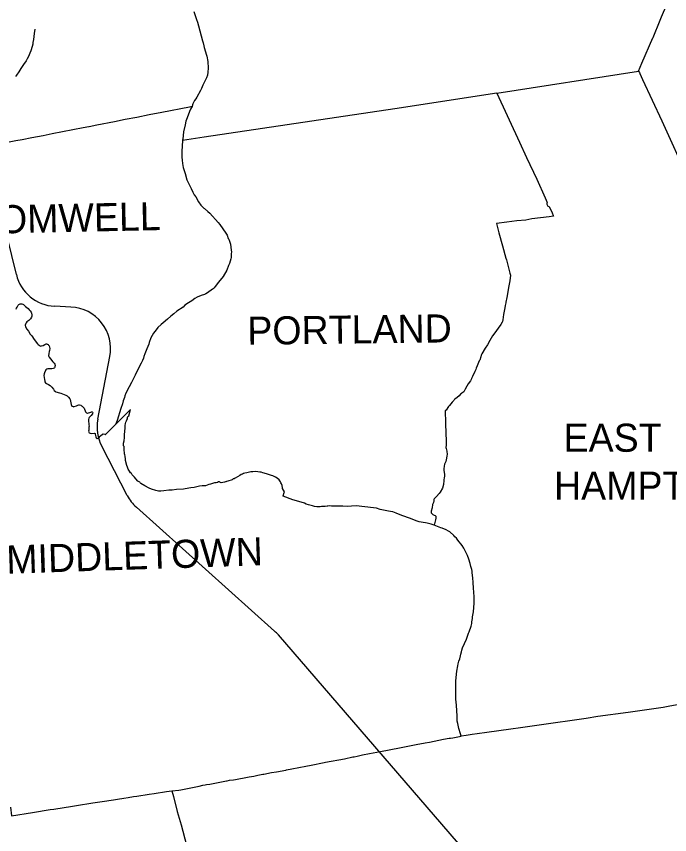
# Model space of a CAD drawing. Extents: x 0 to 2603, y -226 to 830.
# Drawn here: x 204.97 to 236.38, y 575 to 614.31 of the extents above; entities that cross this region are included whole.
import ezdxf

# ---------------------------------------------------------------- set-up
doc = ezdxf.new("R2010")
doc.units = 0
for name, color, linetype in [('CT_TSH_Map_Districts', 7, 'Continuous'), ('CT_TSH_Map_Interstate_Roads', 7, 'Continuous'), ('CT_TSH_Map_Town_Limits', 7, 'Continuous'), ('CT_TSH_Map_Town_Text', 7, 'Continuous'), ('CT_TSH_Map_US_and_State_Routes', 7, 'Continuous')]:
    doc.layers.add(name, color=color, linetype=linetype)

msp = doc.modelspace()

# ---------------------------------------------------------------- linework, layer by layer
at = {"layer": 'CT_TSH_Map_Districts'}
for points in [[(234.884, 611.677), (235.041, 612.051), (235.566, 613.271), (235.579, 613.297), (235.927, 614.12), (235.983, 614.28), (236.084, 614.51), (236.428, 615.301), (240.127, 616.807), (239.953, 617.904), (239.072, 619.882), (239.607, 620.4), (239.988, 620.781), (244.272, 621.425)], [(228.072, 610.617), (234.884, 611.677)], [(228.072, 610.617), (223.173, 609.87), (214.002, 608.502), (212.956, 608.343)], [(212.956, 608.343), (212.919, 607.819), (212.92, 607.548), (212.941, 607.396), (212.953, 607.242), (212.989, 607.041), (213.077, 606.758), (213.166, 606.45), (213.207, 606.351), (213.292, 606.189), (213.377, 606.037), (213.45, 605.861), (213.517, 605.736), (213.592, 605.636), (213.728, 605.397), (213.834, 605.242), (213.98, 605.086), (214.009, 605.072), (214.182, 604.924), (214.267, 604.843), (214.672, 604.397), (214.748, 604.3), (215.04, 603.891), (215.098, 603.801), (215.157, 603.637), (215.18, 603.603), (215.263, 603.365), (215.302, 603.068), (215.307, 603.001), (215.301, 602.894), (215.296, 602.882), (215.291, 602.725), (215.278, 602.658), (215.212, 602.439), (215.175, 602.33), (215.083, 602.105), (214.905, 601.801), (214.686, 601.533), (214.532, 601.323), (214.486, 601.269), (214.43, 601.211), (214.407, 601.198), (214.157, 601.022), (214.086, 600.979), (214.014, 600.94), (213.85, 600.892), (213.657, 600.81), (213.545, 600.745), (213.411, 600.646), (213.242, 600.544), (213.074, 600.424), (212.982, 600.341), (212.687, 600.141), (212.544, 600.015), (212.394, 599.906), (212.241, 599.766), (212.026, 599.579), (211.937, 599.507), (211.773, 599.352), (211.685, 599.251), (211.559, 599.086), (211.439, 598.863), (211.357, 598.641), (211.338, 598.562), (211.249, 598.338), (211.142, 598.086), (211.1, 597.968), (211.077, 597.882), (211.028, 597.767), (210.97, 597.649), (210.802, 597.336), (210.681, 597.076), (210.502, 596.719), (210.399, 596.505), (210.228, 596.208), (210.182, 596.071), (210.16, 595.993), (210.102, 595.839), (210.065, 595.685), (209.984, 595.472), (209.811, 594.898), (209.757, 594.733), (209.758, 594.717)], [(213.773, 591.73), (213.517, 591.674), (213.357, 591.663), (213.259, 591.647), (213.176, 591.619), (213.091, 591.61), (213.004, 591.593), (212.661, 591.577), (212.462, 591.544), (212.37, 591.545), (212.307, 591.54), (212.066, 591.504), (211.907, 591.492), (211.799, 591.498), (211.681, 591.524), (211.47, 591.596), (211.359, 591.638), (211.14, 591.746), (210.961, 591.861), (210.919, 591.898), (210.899, 591.923), (210.815, 591.974), (210.707, 592.091), (210.643, 592.175), (210.533, 592.288), (210.499, 592.341), (210.459, 592.383), (210.402, 592.46), (210.352, 592.55), (210.308, 592.647), (210.276, 592.732), (210.215, 592.967), (210.223, 593.027), (210.192, 593.185), (210.186, 593.239), (210.172, 593.288), (210.155, 593.521), (210.155, 593.614), (210.145, 593.644), (210.124, 593.68), (210.118, 593.719), (210.122, 593.796), (210.149, 593.907), (210.165, 594.072), (210.164, 594.198), (210.204, 594.538), (210.198, 594.647), (210.215, 594.748), (210.236, 594.81), (210.266, 594.871), (210.287, 594.928), (210.311, 594.971), (210.317, 595.058), (210.331, 595.09), (210.374, 595.113), (210.455, 595.413), (209.758, 594.717)], [(225.049, 589.87), (224.908, 589.917), (224.725, 589.964), (224.635, 589.968), (224.525, 589.989), (224.431, 589.999), (224.335, 590.022), (224.186, 590.069), (223.912, 590.183), (223.497, 590.325), (223.23, 590.444), (223.145, 590.476), (223.069, 590.496), (222.955, 590.517), (222.867, 590.541), (222.616, 590.583), (222.461, 590.619), (222.279, 590.676), (222.136, 590.7), (221.731, 590.751), (221.301, 590.789), (221.088, 590.773), (220.876, 590.763), (220.668, 590.772), (220.125, 590.776), (220.016, 590.786), (219.944, 590.774), (219.916, 590.777), (219.822, 590.765), (219.731, 590.763), (219.637, 590.756), (219.583, 590.743), (219.41, 590.749), (219.307, 590.765), (219.209, 590.788), (219.082, 590.826), (219.007, 590.835), (218.903, 590.875), (218.822, 590.912), (218.444, 591.026), (218.259, 591.076), (217.791, 591.25), (217.797, 591.278), (217.848, 591.426), (217.855, 591.459), (217.864, 591.468), (217.771, 591.624), (217.757, 591.66), (217.741, 591.767), (217.714, 591.853), (217.69, 591.902), (217.667, 591.937), (217.644, 591.986), (217.599, 592.045), (217.506, 592.122), (217.426, 592.164), (217.356, 592.207), (217.296, 592.225), (217.233, 592.254), (217.145, 592.28), (216.997, 592.335), (216.824, 592.37), (216.744, 592.405), (216.671, 592.414), (216.586, 592.432), (216.451, 592.433), (216.339, 592.427), (216.249, 592.417), (216.048, 592.38), (215.958, 592.359), (215.883, 592.337), (215.847, 592.315), (215.773, 592.295), (215.712, 592.241), (215.481, 592.115), (215.435, 592.096), (215.397, 592.087), (215.379, 592.067), (215.337, 592.039), (215.135, 591.975), (215.065, 591.953), (215.04, 591.952), (215.017, 591.938), (214.983, 591.925), (214.89, 591.907), (214.812, 591.901), (214.753, 591.927), (214.731, 591.947), (214.66, 591.941), (214.656, 591.928), (214.636, 591.909), (214.578, 591.892), (214.503, 591.896), (214.394, 591.86), (214.309, 591.832), (214.226, 591.818), (214.057, 591.754), (214.026, 591.757), (213.966, 591.752), (213.905, 591.75), (213.773, 591.73)], [(226.349, 579.726), (226.325, 579.833), (226.247, 580.094), (226.188, 580.338), (226.17, 580.445), (226.165, 580.68), (226.129, 581.223), (226.1, 581.496), (226.105, 581.645), (226.096, 582.142), (226.099, 582.363), (226.124, 582.697), (226.142, 582.849), (226.194, 583.107), (226.211, 583.198), (226.249, 583.334), (226.287, 583.445), (226.322, 583.583), (226.333, 583.661), (226.373, 583.777), (226.389, 583.861), (226.423, 583.965), (226.514, 584.178), (226.61, 584.384), (226.711, 584.668), (226.741, 584.732), (226.834, 585.014), (226.866, 585.144), (226.871, 585.219), (226.887, 585.292), (226.893, 585.385), (226.905, 585.461), (226.923, 585.541), (226.943, 585.699), (226.977, 586.119), (226.988, 586.418), (226.967, 586.64), (226.956, 586.833), (226.931, 587.105), (226.919, 587.339), (226.891, 587.567), (226.887, 587.646), (226.872, 587.729), (226.824, 587.882), (226.789, 588.026), (226.716, 588.222), (226.655, 588.402), (226.537, 588.654), (226.487, 588.75), (226.399, 588.892), (226.19, 589.146), (226.123, 589.236), (226.051, 589.307), (226.002, 589.367), (225.807, 589.539), (225.753, 589.579), (225.637, 589.646), (225.44, 589.724), (225.382, 589.737), (225.063, 589.86), (225.049, 589.87)], [(212.436, 577.103), (212.779, 577.13), (212.872, 577.144), (213.755, 577.331), (213.94, 577.374), (214.047, 577.394), (214.109, 577.398), (214.27, 577.421), (215.068, 577.574), (215.111, 577.58), (215.221, 577.606), (215.405, 577.625), (215.499, 577.651), (215.584, 577.668), (216.007, 577.737), (216.157, 577.769), (216.379, 577.806), (216.576, 577.847), (216.812, 577.894), (216.862, 577.908), (217.239, 577.975), (217.471, 578.008), (217.925, 578.1), (217.952, 578.103), (218.218, 578.161), (218.881, 578.282), (219.136, 578.338), (219.761, 578.461), (219.834, 578.476), (220.744, 578.638), (221.139, 578.73), (221.218, 578.738), (221.352, 578.77), (221.476, 578.796), (221.604, 578.828), (221.95, 578.887), (222.471, 578.993), (223.397, 579.171), (224.186, 579.32), (224.62, 579.411), (224.831, 579.443), (225.503, 579.576), (225.773, 579.623), (225.841, 579.632), (225.962, 579.652), (226.108, 579.684), (226.349, 579.726)], [(212.436, 577.103), (212.517, 576.826), (212.708, 576.115), (212.888, 575.462), (213.152, 574.484)]]:
    msp.add_lwpolyline(points, dxfattribs=at)
at = {"layer": 'CT_TSH_Map_Interstate_Roads'}
for points in [[(205.85, 613.695), (205.824, 613.48), (205.79, 613.199)], [(205.768, 613.051), (205.753, 612.972), (205.733, 612.863), (205.668, 612.652), (205.619, 612.538), (205.546, 612.38), (205.486, 612.268)], [(205.79, 613.199), (205.768, 613.051)], [(205.486, 612.268), (205.433, 612.173), (205.311, 611.987), (205.187, 611.796), (205.084, 611.638), (204.97, 611.479)], [(204.97, 611.479), (204.929, 611.423)]]:
    msp.add_lwpolyline(points, dxfattribs=at)
at = {"layer": 'CT_TSH_Map_Town_Limits'}
for points in [[(234.884, 611.677), (235.041, 612.051), (235.566, 613.271), (235.579, 613.297), (235.927, 614.12), (235.983, 614.28), (236.084, 614.51), (236.428, 615.301), (240.127, 616.807), (239.953, 617.904), (239.072, 619.882), (239.607, 620.4), (239.988, 620.781), (244.272, 621.425)], [(213.495, 614.539), (213.628, 614.158), (213.677, 614.031), (213.722, 613.844), (213.795, 613.607), (213.915, 613.133), (213.945, 613.038), (213.975, 612.89), (213.997, 612.817), (214.018, 612.767), (214.1, 612.482), (214.121, 612.399), (214.169, 612.132), (214.189, 611.818), (214.178, 611.621), (214.153, 611.478), (214.109, 611.346), (214.067, 611.252), (213.999, 611.126), (213.977, 611.097), (213.941, 611.002), (213.868, 610.832), (213.826, 610.747), (213.647, 610.425), (213.597, 610.342), (213.539, 610.26), (213.446, 610.1), (213.43, 610.051), (213.423, 609.978)], [(228.072, 610.617), (234.884, 611.677)], [(234.884, 611.677), (234.922, 611.605), (234.945, 611.566), (235.077, 611.27), (235.998, 609.281), (237.269, 606.502), (239.719, 601.253), (240.373, 599.873), (240.571, 599.445), (240.652, 599.27), (240.867, 598.805), (240.916, 598.702), (241.403, 597.685), (241.795, 596.836), (241.83, 596.77)], [(228.072, 610.617), (223.173, 609.87), (214.002, 608.502), (212.956, 608.343)], [(228.072, 610.617), (229.157, 608.258), (229.496, 607.532), (229.986, 606.482), (230.39, 605.58), (230.487, 605.366), (230.487, 605.361), (230.479, 605.335), (230.475, 605.289), (230.489, 605.245), (230.524, 605.195), (230.579, 605.172), (230.582, 605.168), (230.723, 604.86), (230.784, 604.732), (230.793, 604.703), (230.58, 604.679), (229.758, 604.572), (229.458, 604.522), (229.031, 604.476), (228.548, 604.412), (228.048, 604.356), (228.172, 603.904), (228.342, 603.282), (228.504, 602.695), (228.531, 602.605), (228.701, 601.964), (228.734, 601.873), (228.689, 601.593), (228.623, 601.277), (228.577, 600.978), (228.544, 600.803), (228.506, 600.581), (228.498, 600.543), (228.474, 600.41), (228.462, 600.308), (228.394, 599.982), (228.362, 599.72), (228.337, 599.64), (228.333, 599.611), (228.256, 599.497), (227.931, 599.044), (227.862, 598.957), (227.799, 598.853), (227.738, 598.734), (227.621, 598.524), (227.508, 598.361), (227.341, 598.093), (227.317, 598.029), (227.298, 597.953), (227.247, 597.797), (227.222, 597.754), (227.118, 597.516), (227.077, 597.406), (227.055, 597.342), (227.011, 597.244), (226.892, 597.005), (226.866, 596.944), (226.858, 596.902), (226.849, 596.896), (226.798, 596.797), (226.698, 596.652), (226.698, 596.649), (226.625, 596.534), (226.545, 596.4), (226.494, 596.307), (226.476, 596.272), (226.394, 596.196), (226.379, 596.188), (226.33, 596.148), (226.254, 596.076), (226.155, 596.002), (226.049, 595.915), (226.021, 595.882), (225.999, 595.849), (225.928, 595.774), (225.799, 595.614), (225.745, 595.56), (225.627, 595.395), (225.59, 595.359), (225.59, 595.27), (225.6, 594.854), (225.609, 594.731), (225.607, 594.599), (225.625, 594.422), (225.639, 593.77), (225.638, 593.714), (225.632, 593.658), (225.621, 593.626), (225.623, 593.586), (225.64, 593.545), (225.667, 593.413), (225.678, 593.258), (225.668, 593.187), (225.645, 593.082), (225.635, 593.004), (225.617, 592.922), (225.558, 592.788), (225.536, 592.703), (225.52, 592.565), (225.525, 592.494)], [(213.423, 609.978), (213.297, 609.949), (211.955, 609.685), (211.36, 609.572), (210.76, 609.453), (210.205, 609.348), (209.692, 609.243), (208.832, 609.076), (208.469, 609.004), (208.446, 608.993), (208.174, 608.951), (206.69, 608.66), (206.258, 608.572), (205.711, 608.47), (205.252, 608.376), (204.946, 608.324), (204.548, 608.245), (204.102, 608.164), (202.012, 607.761), (201.589, 607.676), (200.476, 607.465), (198.272, 607.038)], [(213.423, 609.978), (213.392, 609.934), (213.347, 609.849), (213.297, 609.734), (213.182, 609.427), (213.121, 609.269), (213.078, 609.098), (213.008, 608.758), (212.971, 608.413), (212.956, 608.362), (212.956, 608.343)], [(212.956, 608.343), (212.919, 607.819), (212.92, 607.548), (212.941, 607.396), (212.953, 607.242), (212.989, 607.041), (213.077, 606.758), (213.166, 606.45), (213.207, 606.351), (213.292, 606.189), (213.377, 606.037), (213.45, 605.861), (213.517, 605.736), (213.592, 605.636), (213.728, 605.397), (213.834, 605.242), (213.98, 605.086), (214.009, 605.072), (214.182, 604.924), (214.267, 604.843), (214.672, 604.397), (214.748, 604.3), (215.04, 603.891), (215.098, 603.801), (215.157, 603.637), (215.18, 603.603), (215.263, 603.365), (215.302, 603.068), (215.307, 603.001), (215.301, 602.894), (215.296, 602.882), (215.291, 602.725), (215.278, 602.658), (215.212, 602.439), (215.175, 602.33), (215.083, 602.105), (214.905, 601.801), (214.686, 601.533), (214.532, 601.323), (214.486, 601.269), (214.43, 601.211), (214.407, 601.198), (214.157, 601.022), (214.086, 600.979), (214.014, 600.94), (213.85, 600.892), (213.657, 600.81), (213.545, 600.745), (213.411, 600.646), (213.242, 600.544), (213.074, 600.424), (212.982, 600.341), (212.687, 600.141), (212.544, 600.015), (212.394, 599.906), (212.241, 599.766), (212.026, 599.579), (211.937, 599.507), (211.773, 599.352), (211.685, 599.251), (211.559, 599.086), (211.439, 598.863), (211.357, 598.641), (211.338, 598.562), (211.249, 598.338), (211.142, 598.086), (211.1, 597.968), (211.077, 597.882), (211.028, 597.767), (210.97, 597.649), (210.802, 597.336), (210.681, 597.076), (210.502, 596.719), (210.399, 596.505), (210.228, 596.208), (210.182, 596.071), (210.16, 595.993), (210.102, 595.839), (210.065, 595.685), (209.984, 595.472), (209.811, 594.898), (209.757, 594.733), (209.758, 594.717)], [(204.954, 600.237), (204.981, 600.286), (205, 600.342), (205.055, 600.428), (205.084, 600.46), (205.117, 600.486), (205.148, 600.498), (205.229, 600.498), (205.275, 600.485), (205.309, 600.467)], [(205.309, 600.467), (205.414, 600.372), (205.543, 600.264), (205.586, 600.212), (205.639, 600.164), (205.677, 600.1), (205.704, 600.04), (205.719, 599.961), (205.715, 599.901), (205.703, 599.858), (205.656, 599.774), (205.575, 599.696), (205.468, 599.626), (205.436, 599.584), (205.406, 599.522), (205.398, 599.47), (205.411, 599.384), (205.478, 599.273), (205.548, 599.186), (205.632, 599.044), (205.708, 598.953), (205.83, 598.777), (205.992, 598.575), (206.02, 598.541), (206.106, 598.482), (206.153, 598.469), (206.183, 598.471), (206.256, 598.495), (206.344, 598.545), (206.402, 598.567), (206.429, 598.569), (206.447, 598.564), (206.491, 598.537), (206.519, 598.506), (206.542, 598.471), (206.565, 598.414), (206.58, 598.354), (206.568, 598.261), (206.551, 598.198), (206.527, 598.116), (206.515, 598.002), (206.546, 597.929), (206.602, 597.847), (206.726, 597.702), (206.786, 597.645), (206.812, 597.596), (206.829, 597.526), (206.826, 597.481), (206.818, 597.452), (206.8, 597.418), (206.788, 597.404), (206.746, 597.386), (206.678, 597.375), (206.56, 597.375), (206.504, 597.378), (206.474, 597.374), (206.427, 597.36), (206.391, 597.317), (206.329, 597.186), (206.309, 597.129), (206.297, 597.051), (206.328, 596.855), (206.332, 596.782), (206.34, 596.747), (206.364, 596.706), (206.417, 596.67), (206.512, 596.617), (206.589, 596.572), (206.668, 596.499), (206.759, 596.392), (206.793, 596.325), (206.844, 596.276), (206.866, 596.263), (207.048, 596.212), (207.11, 596.196), (207.347, 596.109), (207.415, 596.07), (207.48, 596.011), (207.542, 595.932), (207.553, 595.899), (207.597, 595.652), (207.633, 595.583), (207.649, 595.583), (207.699, 595.557), (207.723, 595.553), (207.748, 595.556), (207.857, 595.596), (207.925, 595.628), (207.977, 595.641), (208.003, 595.641), (208.063, 595.623), (208.095, 595.602), (208.129, 595.574), (208.166, 595.552), (208.224, 595.482), (208.299, 595.309), (208.312, 595.287), (208.344, 595.254), (208.366, 595.246), (208.389, 595.245), (208.549, 595.292)], [(208.549, 595.292), (208.589, 595.309), (208.608, 595.309), (208.635, 595.291), (208.64, 595.257), (208.635, 595.231), (208.626, 595.21), (208.566, 595.13), (208.503, 595.066), (208.474, 595.028), (208.456, 594.996), (208.443, 594.938), (208.44, 594.901), (208.46, 594.677), (208.468, 594.623), (208.459, 594.568), (208.448, 594.422), (208.444, 594.383), (208.448, 594.332), (208.464, 594.299), (208.512, 594.275), (208.564, 594.272), (208.727, 594.281), (208.752, 594.269), (208.765, 594.234), (208.793, 594.099), (208.81, 594.054), (208.834, 594.031), (208.851, 594.027), (208.907, 594.04), (208.933, 594.054), (208.954, 594.072), (208.982, 594.114), (209.014, 594.15), (209.109, 594.237), (209.137, 594.249), (209.215, 594.232), (209.238, 594.223), (209.247, 594.226), (209.758, 594.717)], [(213.773, 591.73), (213.517, 591.674), (213.357, 591.663), (213.259, 591.647), (213.176, 591.619), (213.091, 591.61), (213.004, 591.593), (212.661, 591.577), (212.462, 591.544), (212.37, 591.545), (212.307, 591.54), (212.066, 591.504), (211.907, 591.492), (211.799, 591.498), (211.681, 591.524), (211.47, 591.596), (211.359, 591.638), (211.14, 591.746), (210.961, 591.861), (210.919, 591.898), (210.899, 591.923), (210.815, 591.974), (210.707, 592.091), (210.643, 592.175), (210.533, 592.288), (210.499, 592.341), (210.459, 592.383), (210.402, 592.46), (210.352, 592.55), (210.308, 592.647), (210.276, 592.732), (210.215, 592.967), (210.223, 593.027), (210.192, 593.185), (210.186, 593.239), (210.172, 593.288), (210.155, 593.521), (210.155, 593.614), (210.145, 593.644), (210.124, 593.68), (210.118, 593.719), (210.122, 593.796), (210.149, 593.907), (210.165, 594.072), (210.164, 594.198), (210.204, 594.538), (210.198, 594.647), (210.215, 594.748), (210.236, 594.81), (210.266, 594.871), (210.287, 594.928), (210.311, 594.971), (210.317, 595.058), (210.331, 595.09), (210.374, 595.113), (210.455, 595.413), (209.758, 594.717)], [(225.049, 589.87), (224.908, 589.917), (224.725, 589.964), (224.635, 589.968), (224.525, 589.989), (224.431, 589.999), (224.335, 590.022), (224.186, 590.069), (223.912, 590.183), (223.497, 590.325), (223.23, 590.444), (223.145, 590.476), (223.069, 590.496), (222.955, 590.517), (222.867, 590.541), (222.616, 590.583), (222.461, 590.619), (222.279, 590.676), (222.136, 590.7), (221.731, 590.751), (221.301, 590.789), (221.088, 590.773), (220.876, 590.763), (220.668, 590.772), (220.125, 590.776), (220.016, 590.786), (219.944, 590.774), (219.916, 590.777), (219.822, 590.765), (219.731, 590.763), (219.637, 590.756), (219.583, 590.743), (219.41, 590.749), (219.307, 590.765), (219.209, 590.788), (219.082, 590.826), (219.007, 590.835), (218.903, 590.875), (218.822, 590.912), (218.444, 591.026), (218.259, 591.076), (217.791, 591.25), (217.797, 591.278), (217.848, 591.426), (217.855, 591.459), (217.864, 591.468), (217.771, 591.624), (217.757, 591.66), (217.741, 591.767), (217.714, 591.853), (217.69, 591.902), (217.667, 591.937), (217.644, 591.986), (217.599, 592.045), (217.506, 592.122), (217.426, 592.164), (217.356, 592.207), (217.296, 592.225), (217.233, 592.254), (217.145, 592.28), (216.997, 592.335), (216.824, 592.37), (216.744, 592.405), (216.671, 592.414), (216.586, 592.432), (216.451, 592.433), (216.339, 592.427), (216.249, 592.417), (216.048, 592.38), (215.958, 592.359), (215.883, 592.337), (215.847, 592.315), (215.773, 592.295), (215.712, 592.241), (215.481, 592.115), (215.435, 592.096), (215.397, 592.087), (215.379, 592.067), (215.337, 592.039), (215.135, 591.975), (215.065, 591.953), (215.04, 591.952), (215.017, 591.938), (214.983, 591.925), (214.89, 591.907), (214.812, 591.901), (214.753, 591.927), (214.731, 591.947), (214.66, 591.941), (214.656, 591.928), (214.636, 591.909), (214.578, 591.892), (214.503, 591.896), (214.394, 591.86), (214.309, 591.832), (214.226, 591.818), (214.057, 591.754), (214.026, 591.757), (213.966, 591.752), (213.905, 591.75), (213.773, 591.73)], [(225.525, 592.494), (225.546, 592.313), (225.554, 592.225), (225.54, 592.121), (225.526, 592.052), (225.526, 592.012), (225.505, 591.82), (225.46, 591.638), (225.338, 591.451), (225.304, 591.388), (225.166, 591.236), (225.075, 591.15), (225.049, 591.121), (225.048, 591.094), (225.042, 591.071), (225.039, 591.027), (225.024, 590.95), (224.97, 590.855), (224.961, 590.697), (224.917, 590.543), (224.913, 590.491), (224.917, 590.458), (224.941, 590.418), (224.999, 590.368), (225.052, 590.346), (225.111, 590.333), (225.127, 590.314), (225.133, 590.29), (225.131, 590.196), (225.116, 590.115), (225.049, 589.87)], [(226.349, 579.726), (226.325, 579.833), (226.247, 580.094), (226.188, 580.338), (226.17, 580.445), (226.165, 580.68), (226.129, 581.223), (226.1, 581.496), (226.105, 581.645), (226.096, 582.142), (226.099, 582.363), (226.124, 582.697), (226.142, 582.849), (226.194, 583.107), (226.211, 583.198), (226.249, 583.334), (226.287, 583.445), (226.322, 583.583), (226.333, 583.661), (226.373, 583.777), (226.389, 583.861), (226.423, 583.965), (226.514, 584.178), (226.61, 584.384), (226.711, 584.668), (226.741, 584.732), (226.834, 585.014), (226.866, 585.144), (226.871, 585.219), (226.887, 585.292), (226.893, 585.385), (226.905, 585.461), (226.923, 585.541), (226.943, 585.699), (226.977, 586.119), (226.988, 586.418), (226.967, 586.64), (226.956, 586.833), (226.931, 587.105), (226.919, 587.339), (226.891, 587.567), (226.887, 587.646), (226.872, 587.729), (226.824, 587.882), (226.789, 588.026), (226.716, 588.222), (226.655, 588.402), (226.537, 588.654), (226.487, 588.75), (226.399, 588.892), (226.19, 589.146), (226.123, 589.236), (226.051, 589.307), (226.002, 589.367), (225.807, 589.539), (225.753, 589.579), (225.637, 589.646), (225.44, 589.724), (225.382, 589.737), (225.063, 589.86), (225.049, 589.87)], [(239.476, 581.714), (236.384, 581.164), (236.063, 581.104), (234.377, 580.866), (232.933, 580.667), (232.367, 580.578), (230.098, 580.254), (229.204, 580.131), (228.737, 580.061), (227.594, 579.901), (227.127, 579.835), (226.889, 579.805), (226.593, 579.751), (226.349, 579.726)], [(212.436, 577.103), (212.779, 577.13), (212.872, 577.144), (213.755, 577.331), (213.94, 577.374), (214.047, 577.394), (214.109, 577.398), (214.27, 577.421), (215.068, 577.574), (215.111, 577.58), (215.221, 577.606), (215.405, 577.625), (215.499, 577.651), (215.584, 577.668), (216.007, 577.737), (216.157, 577.769), (216.379, 577.806), (216.576, 577.847), (216.812, 577.894), (216.862, 577.908), (217.239, 577.975), (217.471, 578.008), (217.925, 578.1), (217.952, 578.103), (218.218, 578.161), (218.881, 578.282), (219.136, 578.338), (219.761, 578.461), (219.834, 578.476), (220.744, 578.638), (221.139, 578.73), (221.218, 578.738), (221.352, 578.77), (221.476, 578.796), (221.604, 578.828), (221.95, 578.887), (222.471, 578.993), (223.397, 579.171), (224.186, 579.32), (224.62, 579.411), (224.831, 579.443), (225.503, 579.576), (225.773, 579.623), (225.841, 579.632), (225.962, 579.652), (226.108, 579.684), (226.349, 579.726)], [(204.682, 576.321), (204.736, 575.893), (205.739, 576.053), (206.59, 576.197), (206.769, 576.223), (207.67, 576.371), (207.856, 576.4), (208.645, 576.517), (209.097, 576.58), (209.647, 576.675), (209.831, 576.704), (210.142, 576.753), (210.35, 576.78), (210.599, 576.823), (210.76, 576.842), (211.346, 576.94), (211.598, 576.975), (212.188, 577.067), (212.436, 577.103)], [(212.436, 577.103), (212.517, 576.826), (212.708, 576.115), (212.888, 575.462), (213.152, 574.484)]]:
    msp.add_lwpolyline(points, dxfattribs=at)
at = {"layer": 'CT_TSH_Map_US_and_State_Routes'}
for p, q in [((204.968, 601.899), (203.659, 607.22)), ((207.595, 600.341), (206.811, 600.38)), ((208.882, 594.951), (209.46, 597.967)), ((210.296, 591.292), (209.071, 593.653)), ((217.386, 584.774), (210.738, 590.722))]:
    msp.add_line(p, q, dxfattribs=at)
msp.add_lwpolyline([(231.461, 568.52), (227.235, 573.408), (217.565, 584.591)], dxfattribs=at)
for centre, start, end in [((206.91, 602.377), 193.8184, 267.1573), ((207.496, 598.343), 349.1521, 87.1573), ((210.846, 594.574), 169.1521, 207.4173), ((212.071, 592.212), 207.4173, 228.1794), ((216.052, 583.283), 40.8478, 48.1794)]:
    msp.add_arc(centre, 2, start, end, dxfattribs=at)

# ---------------------------------------------------------------- texts
at = {"layer": 'CT_TSH_Map_Town_Text'}
for s, rotation, p in [('CROMWELL', 1.1993, (201.492, 603.82)), ('PORTLAND', 0.7091, (216.08, 598.525)), ('MIDDLETOWN', 1.8898, (204.507, 587.529))]:
    msp.add_text(s, height=1.35, rotation=rotation, dxfattribs=at).set_placement(p)
for s, p in [('EAST', (231.278, 593.388)), ('HAMPTON', (230.818, 591.083))]:
    msp.add_text(s, height=1.35, dxfattribs=at).set_placement(p)

doc.saveas('drawing.dxf')
